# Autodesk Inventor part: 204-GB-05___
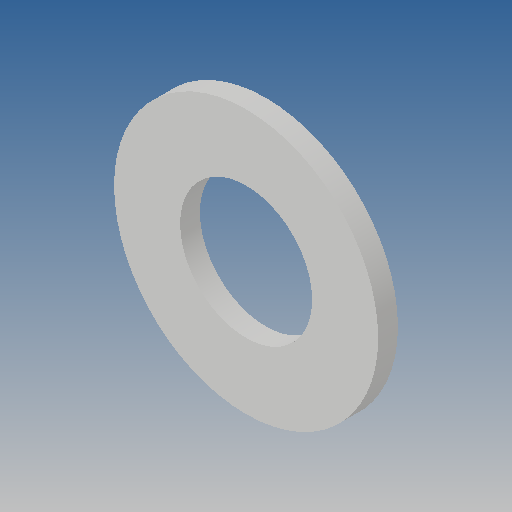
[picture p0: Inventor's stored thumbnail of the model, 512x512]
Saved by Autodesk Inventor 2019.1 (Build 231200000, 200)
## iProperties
Created: 2012-09
Part Number: 204-GB-05___
Material: Ogólny
Document SubType Name: Modeling
Designer: CADENGINEERING4
Density: 1 g/cm^3
Appearance: Domyślna
Author: CADENGINEERING4
Revision Number: ÈÎºÎ
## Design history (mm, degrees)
feature "NONE"
node "Bryła1"
